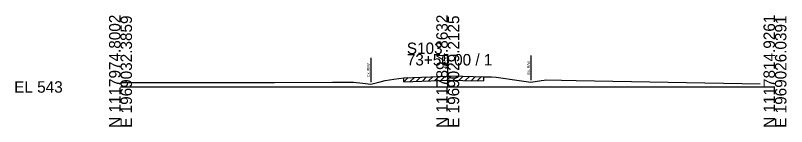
# Model space of a CAD drawing. Extents: x -26 to 163, y -10 to 24018.
# Drawn here: x -25.7 to 162.8, y 21490.3 to 21517.5 of the extents above; entities that cross this region are included whole.
import ezdxf

# ---------------------------------------------------------------- set-up
doc = ezdxf.new("R2010")
doc.units = 0
for name, color, linetype in [('RD_GPK_XS_Cell', 7, 'Continuous'), ('RD_XS_ExGround', 7, 'Continuous'), ('RD_XS_ExPaveRet', 7, 'Continuous'), ('RD_XS_ExRW', 7, 'Continuous'), ('RD_XS_TX_Elev_EX', 7, 'Continuous')]:
    doc.layers.add(name, color=color, linetype=linetype)

msp = doc.modelspace()

# ---------------------------------------------------------------- linework, layer by layer
at = {"layer": 'RD_GPK_XS_Cell'}
for p, q in [((80, 21500), (80, 21508.06)), ((0, 21500), (80, 21500)), ((80, 21500), (160, 21500))]:
    msp.add_line(p, q, dxfattribs=at)
at = {"layer": 'RD_XS_ExGround'}
msp.add_lwpolyline([(0, 21501.12), (3.84, 21501.13), (37.61, 21501.07), (51.79, 21501.2), (57, 21501.21), (59.27, 21500.93), (61.17, 21500.65), (63.13, 21501.14), (64.68, 21501.57), (66.82, 21501.89), (69.3, 21502.25), (75.84, 21502.5), (80, 21502.67), (80.5, 21502.69), (83.72, 21502.61), (88.78, 21502.52), (90.68, 21502.46), (91.83, 21502.42), (97.47, 21501.61), (100.33, 21501.2), (102.91, 21501.58), (104.22, 21501.74), (111.39, 21501.61), (156.35, 21500.78)], dxfattribs=at)
at = {"layer": 'RD_XS_ExPaveRet'}
for p, q in [((69.3, 21501.25), (70.34, 21502.29)), ((69.3, 21501.25), (69.3, 21502.25)), ((70.8, 21501.31), (71.84, 21502.35)), ((72.3, 21501.37), (73.34, 21502.41)), ((73.8, 21501.42), (74.84, 21502.46)), ((75.3, 21501.48), (76.34, 21502.52)), ((76.8, 21501.54), (77.84, 21502.58)), ((78.3, 21501.6), (79.34, 21502.64)), ((79.8, 21501.66), (80.82, 21502.68)), ((81.3, 21501.67), (82.28, 21502.64)), ((82.8, 21501.63), (83.78, 21502.61)), ((84.3, 21501.6), (85.28, 21502.58)), ((85.8, 21501.57), (86.78, 21502.56)), ((87.3, 21501.55), (88.28, 21502.53)), ((88.78, 21502.52), (88.78, 21501.52)), ((69.3, 21501.25), (75.84, 21501.5)), ((75.84, 21501.5), (80, 21501.67)), ((80, 21501.67), (80.5, 21501.69)), ((80.5, 21501.69), (83.72, 21501.61)), ((83.72, 21501.61), (88.78, 21501.52))]:
    msp.add_line(p, q, dxfattribs=at)
at = {"layer": 'RD_XS_ExRW'}
for p, q in [((61.17, 21507.15), (61.17, 21501.15)), ((100.33, 21507.7), (100.33, 21501.7))]:
    msp.add_line(p, q, dxfattribs=at)

# ---------------------------------------------------------------- texts
at = {"layer": 'RD_GPK_XS_Cell'}
for s, p in [('N 1117974.8002', (0, 21490)), ('E 1969032.3859', (2.8, 21490)), ('N 1117894.8632', (80, 21490)), ('E 1969029.2125', (82.8, 21490)), ('N 1117814.9261', (160, 21490)), ('E 1969026.0391', (162.8, 21490))]:
    msp.add_text(s, height=2.8, rotation=90, dxfattribs=at).set_placement(p)
for s, p in [('S103', (70, 21508.06)), ('73+50.00 / 1', (70, 21505.26)), ('EL 543', (-26, 21498.6))]:
    msp.add_text(s, height=2.8, dxfattribs=at).set_placement(p)
at = {"layer": 'RD_XS_ExRW'}
for p in [(100.08, 21503.04), (60.92, 21502.49)]:
    msp.add_text('Ex. R/W ', height=0.65, rotation=90, dxfattribs=at).set_placement(p)
at = {"layer": 'RD_XS_TX_Elev_EX'}
msp.add_text('545.67', height=0.8, rotation=90, dxfattribs=at).set_placement((79.9, 21504.67))

doc.saveas('drawing.dxf')
